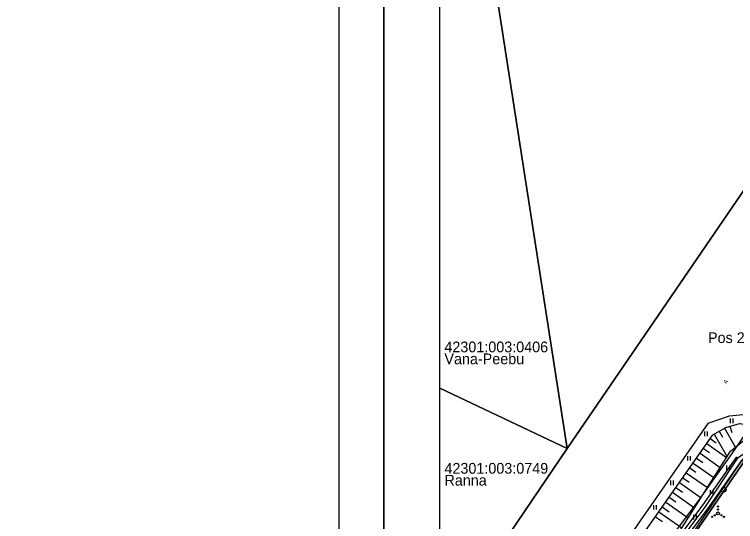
# Model space of a CAD drawing. Extents: x 599446 to 599962, y 6608194 to 6608886.
# Drawn here: x 599659.3 to 599780.3, y 6608574.4 to 6608659.5 of the extents above; entities that cross this region are included whole.
import ezdxf

# ---------------------------------------------------------------- set-up
doc = ezdxf.new("R2010")
doc.units = 0
for name, color, linetype in [('HALJASTUS', 7, 'Continuous'), ('KASUTUSALA', 7, 'Continuous'), ('MPKAABEL', 7, 'Continuous'), ('PIIR', 7, 'Continuous'), ('PR_SIDE', 7, 'Continuous'), ('RELJEEF', 7, 'Continuous'), ('TEE', 7, 'Continuous'), ('VORMISTUS_2', 7, 'Continuous')]:
    doc.layers.add(name, color=color, linetype=linetype)

msp = doc.modelspace()

# ---------------------------------------------------------------- linework, layer by layer
at = {"layer": 'HALJASTUS'}
for p, q in [((599779.38, 6608591.7), (599779.38, 6608590.93)), ((599779.84, 6608591.7), (599779.84, 6608590.93)), ((599775.11, 6608589.52), (599775.11, 6608588.76)), ((599775.56, 6608589.52), (599775.56, 6608588.76)), ((599772.26, 6608585.42), (599772.26, 6608584.65)), ((599772.71, 6608585.42), (599772.71, 6608584.65)), ((599778.8, 6608583.86), (599778.8, 6608583.1)), ((599779.26, 6608583.86), (599779.26, 6608583.1)), ((599769.41, 6608581.31), (599769.41, 6608580.55)), ((599769.86, 6608581.31), (599769.86, 6608580.55)), ((599776.02, 6608579.71), (599776.02, 6608578.95)), ((599776.48, 6608579.71), (599776.48, 6608578.95)), ((599766.56, 6608577.2), (599766.56, 6608576.44)), ((599767.01, 6608577.2), (599767.01, 6608576.44)), ((599773.24, 6608575.56), (599773.24, 6608574.8)), ((599773.69, 6608575.56), (599773.69, 6608574.8))]:
    msp.add_line(p, q, dxfattribs=at)
msp.add_lwpolyline([(599745.5, 6608533.61), (599751.76, 6608542.41), (599769.13, 6608566.52), (599781.31, 6608584.54), (599784.7, 6608586.73), (599788.56, 6608586.95), (599800.79, 6608585.08), (599817.33, 6608582.92), (599820.15, 6608581.03), (599820.84, 6608579.49)], dxfattribs=at)
for centre, radius in [((599778.31, 6608579.77), 0.4), ((599777.37, 6608576.95), 0.1), ((599777.37, 6608576.45), 0.1), ((599776.37, 6608575.23), 0.1), ((599776.81, 6608575.48), 0.1), ((599777.37, 6608575.8), 0.25), ((599777.94, 6608575.48), 0.1), ((599778.37, 6608575.23), 0.1)]:
    msp.add_circle(centre, radius, dxfattribs=at)
at = {"layer": 'KASUTUSALA'}
for points in [[(599664.6, 6608420.14), (599679.58, 6608441.05), (599695.18, 6608463.08), (599714.02, 6608490.66), (599723.56, 6608504.02), (599729.67, 6608515.64), (599742.57, 6608533.81), (599749.11, 6608542.06), (599759.78, 6608557.98), (599766.81, 6608568.23), (599773.98, 6608577.74), (599779.71, 6608585.87), (599791.27, 6608602.69), (599792.26, 6608607.28), (599805.5, 6608627.57), (599816.14, 6608643.34), (599826.26, 6608657.95), (599831.93, 6608665.81)], [(599833.56, 6608664.66), (599827.9, 6608656.79), (599817.79, 6608642.21), (599807.17, 6608626.46), (599794.14, 6608606.49), (599793.14, 6608601.88), (599784.35, 6608589.09), (599785.08, 6608589.36), (599783.13, 6608586.52), (599783.01, 6608586.48), (599781.3, 6608584.67), (599775.61, 6608576.57), (599768.44, 6608567.06), (599761.44, 6608556.85), (599750.73, 6608540.88), (599744.17, 6608532.61), (599731.38, 6608514.59), (599725.26, 6608502.97), (599715.66, 6608489.51), (599696.83, 6608461.94), (599681.21, 6608439.9), (599666.29, 6608419.07)]]:
    msp.add_lwpolyline(points, dxfattribs=at)
at = {"layer": 'MPKAABEL'}
msp.add_lwpolyline([(599744.32, 6608533.61), (599750.33, 6608541.17), (599756.34, 6608550.17), (599761.02, 6608557.13), (599768.15, 6608567.48), (599775.21, 6608576.87), (599780.73, 6608585.16), (599782.28, 6608586.26)], dxfattribs=at)
at = {"layer": 'PIIR'}
for points in [[(599735.83, 6608691.11), (599752.04, 6608586.7), (599730.69, 6608596.81)], [(599730.69, 6608555.17), (599752.04, 6608586.7), (599810.31, 6608671.87), (599822.96, 6608691.11)], [(599806.09, 6608691.11), (599810.31, 6608671.87), (599752.04, 6608586.7), (599735.83, 6608691.11)], [(599851.22, 6608691.11), (599817.31, 6608639.31), (599788.83, 6608594.82), (599746.81, 6608533.61)], [(599730.69, 6608596.81), (599752.04, 6608586.7), (599730.69, 6608555.17)], [(599746.81, 6608533.61), (599788.83, 6608594.82), (599828.73, 6608587.98), (599854.44, 6608583.32)]]:
    msp.add_lwpolyline(points, dxfattribs=at)
at = {"layer": 'PR_SIDE'}
msp.add_lwpolyline([(599666.23, 6608401.55), (599662.07, 6608402.56), (599660.26, 6608402.27), (599659.38, 6608402.48), (599659.32, 6608407.89), (599659.48, 6608408.77), (599665.44, 6608419.61), (599680.4, 6608440.48), (599696.01, 6608462.51), (599714.84, 6608490.08), (599724.41, 6608503.49), (599730.53, 6608515.12), (599743.37, 6608533.21), (599749.92, 6608541.47), (599760.61, 6608557.42), (599767.63, 6608567.64), (599774.8, 6608577.16), (599780.53, 6608585.3)], dxfattribs=at)
at = {"layer": 'RELJEEF'}
for p, q in [((599777.57, 6608589.59), (599778.14, 6608588.58)), ((599778.43, 6608590.08), (599780.28, 6608586.88)), ((599779.37, 6608590.41), (599779.66, 6608589.37)), ((599776.06, 6608588.34), (599777.05, 6608587.65)), ((599776.7, 6608589.09), (599778.88, 6608585.29)), ((599775.48, 6608587.52), (599778.81, 6608585.19)), ((599774.91, 6608586.7), (599775.92, 6608586)), ((599773.76, 6608585.07), (599774.79, 6608584.34)), ((599774.34, 6608585.89), (599777.74, 6608583.5)), ((599773.19, 6608584.25), (599776.66, 6608581.81)), ((599772.04, 6608582.61), (599775.58, 6608580.12)), ((599772.61, 6608583.43), (599773.66, 6608582.69)), ((599771.46, 6608581.79), (599772.54, 6608581.04)), ((599770.31, 6608580.16), (599771.41, 6608579.39)), ((599770.89, 6608580.98), (599774.51, 6608578.43)), ((599769.74, 6608579.34), (599773.43, 6608576.75)), ((599768.59, 6608577.7), (599772.35, 6608575.06)), ((599769.16, 6608578.52), (599770.28, 6608577.74)), ((599768.01, 6608576.88), (599769.15, 6608576.08)), ((599766.86, 6608575.25), (599768.03, 6608574.43)), ((599767.44, 6608576.07), (599771.28, 6608573.37))]:
    msp.add_line(p, q, dxfattribs=at)
for points in [[(599738.5, 6608533.61), (599747.58, 6608546.59), (599763.36, 6608570.26), (599776.5, 6608588.97), (599778.68, 6608590.23), (599780.97, 6608590.85), (599782.59, 6608590.67), (599789.07, 6608589.81), (599801, 6608587.05), (599825.73, 6608582.84), (599838.46, 6608580.71), (599854.44, 6608577.46)], [(599743.91, 6608533.61), (599750.95, 6608543.21), (599767.63, 6608567.64), (599779.48, 6608586.23), (599782.15, 6608588.41), (599783.35, 6608588.88), (599788.84, 6608588.63), (599800.85, 6608586.45), (599825.65, 6608582.15), (599838.44, 6608580.16), (599854.44, 6608577.34)]]:
    msp.add_lwpolyline(points, dxfattribs=at)
at = {"layer": 'TEE'}
msp.add_lwpolyline([(599854.44, 6608578.65), (599844.62, 6608580.25), (599826.08, 6608583.47), (599801.33, 6608588.14), (599788.81, 6608590.96), (599783.36, 6608592.52), (599779.23, 6608592.08), (599775.66, 6608590.88), (599762.01, 6608571.26), (599745.77, 6608547.63), (599736.47, 6608533.61)], dxfattribs=at)
at = {"layer": 'VORMISTUS_2'}
for points in [[(599713.81, 6608728.61), (599871.31, 6608728.61), (599871.31, 6608505.86), (599713.81, 6608505.86)], [(599721.31, 6608514.11), (599863.81, 6608514.11), (599863.81, 6608720.36), (599721.31, 6608720.36)], [(599721.31, 6608720.36), (599863.81, 6608720.36), (599863.81, 6608514.11), (599721.31, 6608514.11)], [(599854.44, 6608533.61), (599730.69, 6608533.61), (599730.69, 6608691.11), (599854.44, 6608691.11)]]:
    msp.add_lwpolyline(points, close=True, dxfattribs=at)

# ---------------------------------------------------------------- texts
at = {"layer": 'PIIR'}
for s, p in [('42301:003:0406', (599731.46, 6608602.82)), ('Vana-Peebu', (599731.46, 6608600.82)), ('42301:003:0749', (599731.47, 6608582.46)), ('Ranna', (599731.47, 6608580.46))]:
    msp.add_text(s, height=1.8, dxfattribs=at).set_placement(p)
at = {"layer": 'TEE'}
msp.add_text('A', height=0.7, rotation=56.1404, dxfattribs=at).set_placement((599778.77, 6608597.42))
at = {"layer": 'VORMISTUS_2'}
msp.add_text('Pos 2', height=1.8, dxfattribs=at).set_placement((599775.68, 6608604.37))

doc.saveas('drawing.dxf')
